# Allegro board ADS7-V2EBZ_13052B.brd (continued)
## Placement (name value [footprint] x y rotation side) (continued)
R339  0  [R0402]  172.85 12.45 180 bottom
R340  4.7K  [R0402]  21.72 124.84 90 bottom
R341  4.7K  [R0402]  151.64 15.88 180 bottom
R342  0  [R0402]  197.49 150.62 0 bottom
R343  100  [R0402]  141.48 37.34 90 bottom
R382  0  [R0402]  185.67 50.04 90 top
R486  10K  [R0402]  37.08 14.61 0 bottom
R518  10  [R0603]  178.44 155.19 180 bottom
R538  4.99K  [R0805]  186.94 150.37 270 bottom
R556  10K  [R0402]  91.44 128.52 180 bottom
R557  10K  [R0402]  87.88 132.08 90 bottom
R558  0  [R0402]  86.23 132.08 90 bottom
R559  0  [R0402]  84.07 131.44 0 bottom
R626  100  [R0201]  64.08 70.48 90 bottom
R627  100  [R0201]  65.1 69.6 90 bottom
R639  33  [R0402]  180.85 57.53 90 top
R640  33  [R0402]  179.58 57.53 90 top
R658  0  [R0402]  164.72 34.92 180 top
R660  0  [R0402]  160.78 35.56 90 top
R664  10K  [R0402]  155.57 32 0 top
R670  100  [R0201]  82.09 70.54 90 bottom
RN1  33  [RN2HV]  199.9 82.93 180 top
RN2  33  [RN2HV]  194.82 82.93 0 top
RN3  33  [RN2HV]  203.71 70.74 270 top
RN4  33  [RN2HV]  203.71 75.82 270 top
RN5  33  [RN2HV]  203.71 60.58 270 top
RN6  33  [RN2HV]  185.93 53.72 180 top
RN7  33  [RN2HV]  180.34 61.85 90 top
RN8  33  [RN2HV]  180.34 66.93 90 top
RN9  33  [RN2HV]  180.34 72.01 90 top
RN10  33  [RN2HV]  192.28 53.72 180 top
RN11  33  [RN2HV]  197.36 53.72 180 top
RN12  33  [RN2HV]  203.71 65.66 270 top
S1  1201M2S3AQE2  [SWTHRAL500W900H450]  201.8 139.06 270 top
S2  EVQ-PAC05R  [SWPANASONIC_EVQPA]  189.36 96.77 180 top
S3  EVQ-PAC05R  [SWPANASONIC_EVQPA]  99.44 24.13 0 top
S4  SDA05H1SBD  [SWSML578W295H214]  47.37 17.91 180 top
S5  EVQ-PAC05R  [SWPANASONIC_EVQPA]  86.36 14.1 0 top
S6  EVQ-PAC05R  [SWPANASONIC_EVQPA]  99.44 14.1 0 top
TP1  GRN  [CNLOOPTP]  48.9 143 0 top
TP2  GRN  [CNLOOPTP]  132.59 137.03 0 top
TP3  GRN  [CNLOOPTP]  167.77 137.03 0 top
TP4  GRN  [CNLOOPTP]  172.34 137.03 0 top
TP5  GRN  [CNLOOPTP]  184.28 118.24 0 top
TP6  GRN  [CNLOOPTP]  175.13 86.23 0 top
TP7  GRN  [CNLOOPTP]  172.09 34.42 0 top
U1  ADP5054ACPZ  [QFN48_7X7_PAD5_6X5_6]  52.58 159.77 90 top
U2  ADP5054ACPZ  [QFN48_7X7_PAD5_6X5_6]  123.7 159.77 90 top
U3  ADM1293-1AACPZ  [QFN16_4X4_PAD2_65X2_65]  16.51 146.18 0 top
U4  ADM1293-1AACPZ  [QFN16_4X4_PAD2_65X2_65]  27.81 146.18 0 top
U5  ADM1293-1AACPZ  [QFN16_4X4_PAD2_65X2_65]  65.66 146.18 0 top
U6  ADM1293-1AACPZ  [QFN16_4X4_PAD2_65X2_65]  87.5 146.18 0 top
U7  ADM1293-1AACPZ  [QFN16_4X4_PAD2_65X2_65]  96.52 146.18 0 top
U8  ADM1293-1AACPZ  [QFN16_4X4_PAD2_65X2_65]  140.97 146.18 0 top
U9  ADM1276-3ACPZ  [QFN20_5X5_PAD3_1X3_1]  192.28 151 0 top
U10  ADM1178-1ARMZ  [RM10]  19.05 124.71 0 top
U11  ADCLK944BCPZ  [QFN16_3X3_PAD1_5X1_5]  118.87 120.14 90 top
U12  AD9577ACPZ  [QFN40_6X6_PAD4_6X4_6]  132.97 118.75 0 top
U13  ADCLK944BCPZ  [QFN16_3X3_PAD1_5X1_5]  146.69 119.76 270 top
U14  ADM1293-1AACPZ  [QFN16_4X4_PAD2_65X2_65]  159.77 112.14 0 top
U15  ADM1293-1AACPZ  [QFN16_4X4_PAD2_65X2_65]  167.39 112.14 0 top
U16  ADM1293-1AACPZ  [QFN16_4X4_PAD2_65X2_65]  173.74 112.14 0 top
U17  ADM1170-2AUJZ  [TSOT-8]  20.19 101.85 180 top
U18  ADP7105ACPZ-1.8  [DFN8_3X3_PAD2_38X1_64]  179.32 104.39 270 top
U19  ADP151AUJZ-1.8-R7  [TSOT-5]  187.58 104.27 180 top
U20  ADP121-AUJZ25R7  [TSOT-5]  193.29 104.27 180 top
U21  ADP1715ARMZ-1.2-R7  [MSOP8]  205.36 104.9 270 top
U22  SN74AVC2T245RSWR  [QFN10_1_8X1_4]  142.11 99.82 0 top
U23  NC7WZ08K8X  [US8]  17.91 90.42 0 top
U24  ADM6306D131ARJZ1R7  [SOT23-5L]  175.51 93.47 0 top
U25  NC7WZ08K8X  [US8]  189.48 87.88 0 top
U26  NC7SV125P5X  [SC70-5-2]  196.09 88.14 270 top
U27  ADP5054ACPZ  [QFN48_7X7_PAD5_6X5_6]  163.19 67.56 0 top
U28  FXL4TD245BQX  [DQFN16_3_5X2_5_PAD2_15X1_15]  175.26 67.95 90 top
U29  ADSP-BF527KBCZ-6A  [CSPBGA208]  192.28 67.69 0 top
U30  NC7WZ04P6X  [SC70]  207.65 64.14 180 top
U31  XC7VX330T-3FFG1157E  [FBGA1156]  67.69 58.04 0 top
U32  ADG812YRUZ  [TSSOP16]  179.2 48.13 0 top
U33  ICS85411AMLF  [SO8]  199.26 39.75 270 top
U34  NC7SZ08M5X  [SOT23-5L]  172.72 41.91 180 top
U35  TPS51200DRCT  [SON10_3X3_PAD2_4X1_65]  159.64 31.75 0 top
U36  PCA9545APW,118  [TSSOP20]  181.48 27.05 90 top
U37  FXL4245MPX  [MLP24_4_5X3_5_PAD3_1X2_1]  154.56 18.67 270 top
U38  M24C64-WMN6TP  [SO8]  169.29 19.05 90 top
U39  TPS51200DRCT  [SON10_3X3_PAD2_4X1_65]  87.38 128.27 180 bottom
U40  SN74LVC1G17DBVR  [SOT23-5L]  175.01 120.52 90 bottom
U41  MX25U3235FM2I-10G  [SOP8_A]  185.42 39.5 0 bottom
U42  ICS85411AMLF  [SO8]  136.4 37.34 90 bottom
U43  NC7SV126P5X  [SC70-5-2]  89.92 16.51 180 bottom
U44  ADCMP671-1YUJZ  [TSOT23_6]  25.78 18.29 180 bottom
V1  27V  [R0603H35]  194.44 95.76 180 bottom
W1  WP22  [TPC45D22]  133.48 127.25 0 top
W2  WP22  [TPC45D22]  135.51 127.25 0 top
W8  WP22  [TPC45D22]  108.08 122.3 0 top
W9  WP22  [TPC45D22]  159.13 118.24 90 top
W10  WP22  [TPC45D22]  108.08 120.27 0 top
W11  WP22  [TPC45D22]  159.13 120.14 90 top
Y1  25.000MEGHZ  [YSML126W98H29]  127.89 112.01 0 top
Y2  24MEGHZ  [YSML197W126H59]  180.85 81.66 90 top

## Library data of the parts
C1 C6 C13 C19 C22 C25 C35 C44 C109 C112 C118 C119 = CAP: User Part Number: UPN; Tolerance: 10; alternate symbols: (C0402H22_ALT,C0201-2,C0402_A,C0402_ALT); part number: CAP_SM-10UF,25V,10,E011786,C1210; tolerance: 10
C2 C3 C38 C47 C49 C50 C113 C116 C117 = CAP: Tolerance: 5; User Part Number: UPN; alternate symbols: (C0402H22_ALT,C0201-2,C0402_A,C0402_ALT); part number: CAP_SM-1000PF,25V,5,E017843,C0402; tolerance: 5
C4 C5 C7-C11 C16 C17 C30-C34 C40-C43 C84 C85 C91-C94 C98 C99 = CAP: User Part Number: UPN; Tolerance: 20; alternate symbols: (C0402H22_ALT,C0201-2,C0402_A,C0402_ALT); part number: CAP_SM-100UF,6.3V,20,E006532,C1210; tolerance: 20
C12 C18 C21 C24 C56 C57 C59 C60 C63 C66 C69-C72 C75-C78 C95 C96 C101 C102 C110 C111 C125-C127 C130 C133 C135-C137 C143-C147 C165 C169 C170 C172 C177 C180-C182 C188-C192 C194 C198 C201 C202 C204 C212 C214 C216 C218 C220-C222 C224-C226 C234 C235 C244 C246 C247 C255 C257-C261 C264 C265 C267 C272 C274 C275 C278 C279 C281-C283 C286 C288 C302 C319 C326 C335 C339 C340 C342-C346 C348 = CAP: Tolerance: 10; User Part Number: UPN; alternate symbols: (C0402H22_ALT,C0201-2,C0402_A,C0402_ALT); part number: CAP_SM-0.1UF,16V,10,E007200,C0402; tolerance: 10; signal model: DEFAULT_CAPACITOR_100000pF_2_1
C14 C15 C20 C23 C26-C28 C39 C122 C123 C128 C129 = CAP: Tolerance: 20; User Part Number: UPN; alternate symbols: (C0402H22_ALT,C0201-2,C0402_A,C0402_ALT); part number: CAP_SM-47UF,16V,20,E013836,C1210-2; tolerance: 20
C29 C54 C149 = CAP: User Part Number: UPN; Tolerance: 10; alternate symbols: (C0402H22_ALT,C0201-2,C0402_A,C0402_ALT); part number: CAP_SM-0.01UF,50V,10,E000421,C0603; tolerance: 10; signal model: DEFAULT_CAPACITOR_10000pF_2_1
C36 C37 C45 C46 C79-C82 C87 C114 C115 C228 = CAP: User Part Number: UPN; Tolerance: 10; alternate symbols: (C0402H22_ALT,C0201-2,C0402_A,C0402_ALT); part number: CAP_SM-1UF,10V,10,E011783,C0603; tolerance: 10
C48 C52 C150 = CAP: User Part Number: UPN; Tolerance: 10; alternate symbols: (C0402H22_ALT,C0201-2,C0402_A,C0402_ALT); part number: CAP_SM-0.1UF,50V,10,E015248,C0603; tolerance: 10; signal model: DEFAULT_CAPACITOR_100000pF_2_1
C51 = CAP: User Part Number: UPN; Tolerance: 10; alternate symbols: (C0402H22_ALT,C0201-2,C0402_A,C0402_ALT); part number: CAP_SM-0.33UF,16V,10,E015523,C0603; tolerance: 10; signal model: DEFAULT_CAPACITOR_330000pF_2_1
C53 = CAP: User Part Number: UPN; Tolerance: 10; alternate symbols: (C0402H22_ALT,C0201-2,C0402_A,C0402_ALT); part number: CAP_SM-1UF,25V,10,E006992,C0603; tolerance: 10; signal model: DEFAULT_CAPACITOR_1e+06pF_2_1
C55 = CAP: User Part Number: UPN; Tolerance: 10; alternate symbols: (C0402H22_ALT,C0201-2,C0402_A,C0402_ALT); part number: CAP_SM-22NF,16V,10,E000327,C0603; tolerance: 10; signal model: DEFAULT_CAPACITOR_22000pF_2_1
C58 C97 C186 C291 = CAPP: User Part Number: UPN; Tolerance: 20; part number: CAPP_SM-330UF,6.3V,20,E000644,C7343H162; tolerance: 20; signal model: DEFAULT_CAPACITOR_3.3e+08pF_N_P
C61 C65 C168 C171 C173 C178 C179 C187 C195-C197 C200 C203 C213 C215 C217 C219 C232 C239 = CAP: Tolerance: 10; User Part Number: UPN; alternate symbols: (C0402H22_ALT,C0201-2,C0402_A,C0402_ALT); part number: CAP_SM-0.01UF,25V,10,E010983,C0402; tolerance: 10; signal model: DEFAULT_CAPACITOR_10000pF_2_1
C62 = CAP: Tolerance: 10; User Part Number: UPN; alternate symbols: (C0402H22_ALT,C0201-2,C0402_A,C0402_ALT); part number: CAP_SM-0.33UF,10V,10,E011273,C0402; tolerance: 10; signal model: DEFAULT_CAPACITOR_100000pF_2_1
C64 = CAP: Tolerance: 10; User Part Number: UPN; alternate symbols: (C0402H22_ALT,C0201-2,C0402_A,C0402_ALT); part number: CAP_SM-0.22UF,10V,10,E011012,C0402; tolerance: 10; signal model: DEFAULT_CAPACITOR_220000pF_2_1
C67 C68 = CAP: Tolerance: 5; User Part Number: UPN; alternate symbols: (C0402H22_ALT,C0201-2,C0402_A,C0402_ALT); part number: CAP_SM-22PF,50V,5,E000265,C0402; tolerance: 5; signal model: DEFAULT_CAPACITOR_22pF_2_1
C73 = CAP: Tolerance: 10; User Part Number: UPN; alternate symbols: (C0402H22_ALT,C0201-2,C0402_A,C0402_ALT); part number: CAP_SM-1UF,10V,10,E011429,C0402; tolerance: 10; signal model: DEFAULT_CAPACITOR_1e+06pF_1_2
C74 = CAP: Tolerance: 10; User Part Number: UPN; alternate symbols: (C0402H22_ALT,C0201-2,C0402_A,C0402_ALT); part number: CAP_SM-0.33UF,10V,10,E011273,C0402; tolerance: 10; signal model: DEFAULT_CAPACITOR_330000pF_1_2
C83 C88 = CAP: User Part Number: UPN; Tolerance: 10; alternate symbols: (C0402H22_ALT,C0201-2,C0402_A,C0402_ALT); part number: CAP_SM-2.2UF,6.3V,10,E006877,C0603; tolerance: 10
C86 = CAP: Tolerance: 10; User Part Number: UPN; alternate symbols: (C0402H22_ALT,C0201-2,C0402_A,C0402_ALT); part number: CAP_SM-0.01UF,25V,10,E019646,C0402; tolerance: 10
C89 = CAP: Tolerance: 10; User Part Number: UPN; alternate symbols: (C0402H22_ALT,C0201-2,C0402_A,C0402_ALT); part number: CAP_SM-0.01UF,25V,10,E019646,C0402; tolerance: 10; signal model: DEFAULT_CAPACITOR_10000pF_2_1
C90 = CAP: Tolerance: 10; User Part Number: UPN; alternate symbols: (C0402H22_ALT,C0201-2,C0402_A,C0402_ALT); part number: CAP_SM-4700PF,50V,10,E000289,C0402; tolerance: 10; signal model: DEFAULT_CAPACITOR_4700pF_1_2
C100 = CAP: Tolerance: 10; User Part Number: UPN; alternate symbols: (C0402H22_ALT,C0201-2,C0402_A,C0402_ALT); part number: CAP_SM-1UF,10V,10,E011429,C0402; tolerance: 10; signal model: DEFAULT_CAPACITOR_100pF_2_1
C103 C120 = CAPP: User Part Number: UPN; Tolerance: 10; part number: CAPP_SM-680UF,6.3V,10,E017133,C7343-43; tolerance: 10; signal model: DEFAULT_CAPACITOR_3.3e+08pF_N_P
C104 C106 = CAP: Tolerance: 0.5PF; User Part Number: UPN; alternate symbols: (C0402H22_ALT,C0201-2,C0402_A,C0402_ALT); part number: CAP_SM-8.2PF,50V,0.5PF,E000302,C0402; tolerance: 0.5PF; signal model: DEFAULT_CAPACITOR_8.2pF_2_1
C105 = CAP: User Part Number: UPN; Tolerance: 10; alternate symbols: (C0402H22_ALT,C0201-2,C0402_A,C0402_ALT); part number: CAP_SM-10000PF,250V,10,E011672,C0805; tolerance: 10; signal model: DEFAULT_CAPACITOR_10000pF_2_1
C107 C108 C121 C124 C132 C141 C142 C229 C230 C251-C254 C263 C273 C285 C292-C294 C303 C304 C327-C330 C336 = CAP: Tolerance: -20/+80; User Part Number: UPN; alternate symbols: (C0402H22_ALT,C0201-2,C0402_A,C0402_ALT); part number: CAP_SM-0.1UF,25V,-20/+80,E011876,C0402; tolerance: -20/+80; signal model: DEFAULT_CAPACITOR_100000pF_2_1
C131 C163 = CAP: User Part Number: UPN; Tolerance: 10; alternate symbols: (C0402H22_ALT,C0201-2,C0402_A,C0402_ALT); part number: CAP_SM-4.7UF,16V,10,E011042,C0805; tolerance: 10; signal model: DEFAULT_CAPACITOR_4.7e+06pF_2_1
C134 C164 = CAP: User Part Number: UPN; Tolerance: 5; alternate symbols: (C0402H22_ALT,C0201-2,C0402_A,C0402_ALT); part number: CAP_SM-1000PF,50V,5,E007908,C0603; tolerance: 5; signal model: DEFAULT_CAPACITOR_1000pF_2_1
C138-C140 C183-C185 = CAP: User Part Number: UPN; Tolerance: 10; alternate symbols: (C0402H22_ALT,C0201-2,C0402_A,C0402_ALT); part number: CAP_SM-10UF,25V,10,E006874,C1206; tolerance: 10; signal model: DEFAULT_CAPACITOR_1e+07pF_2_1
C148 = CAP: User Part Number: UPN; Tolerance: 10; alternate symbols: (C0402H22_ALT,C0201-2,C0402_A,C0402_ALT); part number: CAP_SM-0.033UF,16V,10,E011751,C0603; tolerance: 10; signal model: DEFAULT_CAPACITOR_33000pF_2_1
C151-C162 C206-C211 = CAP: Tolerance: 20; User Part Number: UPN; alternate symbols: (C0402H22_ALT,C0201-2,C0402_A,C0402_ALT); part number: CAP_SM-4.7UF,10V,20,E015601,C0402; tolerance: 20
C166 C167 C289 C307 = CAP: User Part Number: UPN; Tolerance: 20; alternate symbols: (C0402H22_ALT,C0201-2,C0402_A,C0402_ALT); part number: CAP_SM-100UF,6.3V,20,E006532,C1210; tolerance: 20; signal model: DEFAULT_CAPACITOR_1e+08pF_2_1
C174-C176 C193 C199 = CAP: User Part Number: UPN; Tolerance: 10; alternate symbols: (C0402H22_ALT,C0201-2,C0402_A,C0402_ALT); part number: CAP_SM-0.1UF,6.3V,10,E011567,C0201; tolerance: 10; signal model: DEFAULT_CAPACITOR_100000pF_2_1
C205 C223 C231 C318 C331 C347 = CAP: User Part Number: UPN; Tolerance: 20; alternate symbols: (C0402H22_ALT,C0201-2,C0402_A,C0402_ALT); part number: CAP_SM-10UF,6.3V,20,E011043,C0805; tolerance: 20; signal model: DEFAULT_CAPACITOR_1e+07pF_2_1
C227 C287 C295-C300 C305 C306 = CAP: Tolerance: 20; User Part Number: UPN; alternate symbols: (C0402H22_ALT,C0201-2,C0402_A,C0402_ALT); part number: CAP_SM-4.7UF,10V,20,E015601,C0402; tolerance: 20; signal model: DEFAULT_CAPACITOR_4.7e+06pF_2_1
C233 = CAP: User Part Number: UPN; Tolerance: 10; alternate symbols: (C0402H22_ALT,C0201-2,C0402_A,C0402_ALT); part number: CAP_SM-0.033UF,16V,10,E011751,C0603; tolerance: 10
C236 C238 = CAP: Tolerance: 10; User Part Number: UPN; alternate symbols: (C0402H22_ALT,C0201-2,C0402_A,C0402_ALT); part number: CAP_SM-1UF,16V,10,E019219,C0402; tolerance: 10
C237 = CAP: User Part Number: UPN; Tolerance: 10; alternate symbols: (C0402H22_ALT,C0201-2,C0402_A,C0402_ALT); part number: CAP_SM-0.33UF,16V,10,E015523,C0603; tolerance: 10
C240 = CAP: User Part Number: UPN; Tolerance: 60; alternate symbols: (C0402H22_ALT,C0201-2,C0402_A,C0402_ALT); part number: CAP_SM-47UF,6.3V,60,E000249,C1210; tolerance: 60; signal model: DEFAULT_CAPACITOR_4.7e+07pF_2_1
C241-C243 C249 C250 C262 C270 C284 C290 C301 C309 C317 = CAP: User Part Number: UPN; Tolerance: 20; alternate symbols: (C0402H22_ALT,C0201-2,C0402_A,C0402_ALT); part number: CAP_SM-100UF,6.3V,20,E016591,C1206H71; tolerance: 20; signal model: DEFAULT_CAPACITOR_1e+08pF_2_1
C245 C248 C256 C266 C268 C269 C276 C277 C280 = CAP: User Part Number: UPN; Tolerance: 10; alternate symbols: (C0402H22_ALT,C0201-2,C0402_A,C0402_ALT); part number: CAP_SM-1UF,10V,10,E011783,C0603; tolerance: 10; signal model: DEFAULT_CAPACITOR_1e+06pF_2_1
C271 = CAP: User Part Number: UPN; Tolerance: 20; alternate symbols: (C0402H22_ALT,C0201-2,C0402_A,C0402_ALT); part number: CAP_SM-47UF,6.3V,20,E006154,C1206; tolerance: 20; signal model: DEFAULT_CAPACITOR_4.7e+07pF_2_1
C308 = CAP: Tolerance: 10; User Part Number: UPN; alternate symbols: (C0402H22_ALT,C0201-2,C0402_A,C0402_ALT); part number: CAP_SM-0.1UF,16V,10,E007200,C0402; tolerance: 10
C310-C312 C314 C315 C320-C322 C324 C325 = CAP: Tolerance: 10; User Part Number: UPN; alternate symbols: (C0402H22_ALT,C0201-2,C0402_A,C0402_ALT); part number: CAP_SM-4.7UF,6.3V,10,E020089,C0402; tolerance: 10; signal model: DEFAULT_CAPACITOR_1e+06pF_2_1
C313 = CAPP: Tolerance: 20; User Part Number: UPN; part number: CAPP_SM-220UF,25V,20,E007635,CPLSML327W327H413; tolerance: 20; signal model: DEFAULT_CAPACITOR_2.2e+08pF_N_P
C316 C323 C332-C334 = CAP: Tolerance: 10; User Part Number: UPN; alternate symbols: (C0402H22_ALT,C0201-2,C0402_A,C0402_ALT); part number: CAP_SM-4.7UF,6.3V,10,E020089,C0402; tolerance: 10; signal model: DEFAULT_CAPACITOR_470000pF_2_1
C337 C338 C341 = CAP: User Part Number: UPN; Tolerance: 10; alternate symbols: (C0402H22_ALT,C0201-2,C0402_A,C0402_ALT); part number: CAP_SM-1UF,16V,10,E006882,C0603; tolerance: 10; signal model: DEFAULT_CAPACITOR_1e+06pF_2_1
CN1-CN18 = CAPARRAY8P: Tolerance: 20; User Part Number: UPN; part number: CAPARRAY8P_SM-1000PF,50V,20,E005848,C-NET8P-0805; tolerance: 20
CR1 = DIOMMSZ2V4T1: User Part Number: UPN; Tolerance: N/A; part number: DIOMMSZ2V4T1_SM-MMSZ4678T1G,1.8V,N/A,E005557,SOD123; tolerance: N/A
CR2 CR4 CR5 = DIOZNR_V2: User Part Number: UPN; Tolerance: N/A; part number: DIOZNR_V2_SM-PGB1010603,24V,N/A,E011584,D0603; tolerance: N/A
D1 = DIO: User Part Number: UPN; Tolerance: N/A; alternate symbols: (DO15_ALT); part number: DIO_SM-SMBJ13A-TR,13V,N/A,E016695,DO214AA1; tolerance: N/A
D2 = DIOSCHOTTKY: User Part Number: UPN; Tolerance: N/A; part number: DIOSCHOTTKY_SM-MBRS540T3G,40V,N/A,E010076,SMC; tolerance: N/A
D3 = DIO: User Part Number: UPN; Tolerance: N/A; alternate symbols: (DO15_ALT); part number: DIO_SM-DL4148,100V,N/A,E001135,DL35; tolerance: N/A
DS1-DS8 DS13 DS15 DS16 DS32 DS39 DS40 = DIOLED: User Part Number: UPN; Tolerance: N/A; part number: DIOLED_SM-AA2214CGSK (GREEN),2.1V,N/A,E015747,LEDSML90W55H55; tolerance: N/A
DS14 DS17 DS18 = DIOLED: User Part Number: UPN; Tolerance: N/A; part number: DIOLED_SM-AA2214SURSK (RED),1.95V,N/A,E015746,LEDSML90W55H55; tolerance: N/A
E1 E2 = FERRITE: User Part Number: UPN; Tolerance: 25; part number: FERRITE_SM-600OHM,25,E014192,L1206-3; tolerance: 25; signal model: DEFAULT_RESISTOR_600OHM_2_1
E3 = FERRITE: User Part Number: UPN; Tolerance: N/A; part number: FERRITE_SM-600OHM,N/A,E002360,L0805; tolerance: N/A; signal model: DEFAULT_RESISTOR_600OHM_2_1
F1 = FSFUSE: User Part Number: UPN; part number: FSFUSE_SM-8A,24V,E017065,TE CONNECTIVITY,1206SFF800F/24-2,SCD-015423,F1206H46,N/A
F2 = FSFUSE: User Part Number: UPN; part number: FSFUSE_SM-0.05A,60V,E017159,BEL FUSE INC,0ZCB0005FF2E,SCD-016141,F1210_A,N/A
F3 = FSFUSE: User Part Number: UPN; part number: FSFUSE_SM-0.50A,6V,E016241,LITTELFUSE,1206L050,SCD-014224,F1206H30,N/A
GP1 = NC2P: User Part Number: UPN; part number: NC2P_SM-JPSLD02,E006230,JPSLD02
J3-J6 = CNBNC5P: User Part Number: UPN; alternate symbols: (CNAMPHENOL132255-11_ALT); part number: CNBNC5P_SM-132255-11,E017863,AMPHENOL CONNEX,132255-11,SCD-016572,CNAMPHENOL132255-11
L1 = IND: Tolerance: 20; User Part Number: UPN; alternate symbols: (L0402-2,L0603_ALT); part number: IND_SM-1.8UH,20,E019861,LSML250W258H122; tolerance: 20
L2 = IND: Tolerance: 20; User Part Number: UPN; alternate symbols: (L0402-2,L0603_ALT); part number: IND_SM-3.3UH,20,E017135,LSML250W258H122; tolerance: 20
L3 L4 L7 L8 L11 L12 = IND: User Part Number: UPN; Tolerance: 20; alternate symbols: (L0402-2,L0603_ALT); part number: IND_SM-4.7UH,20,E013623,LSMSQ157H122; tolerance: 20
L5 L6 L9 L10 = IND: Tolerance: 20; User Part Number: UPN; alternate symbols: (L0402-2,L0603_ALT); part number: IND_SM-1.2UH,20,E018077,LSML208W216H122; tolerance: 20
P1 = CN400P_A_K: User Part Number: UPN; part number: CN400P_A_K_SM-ASP-134486-01,E011412,CNSAMTECASP-134486-01
P2 P11 = CN3P: User Part Number: UPN; part number: CN3P_TH-MOLEX22-23-2031,E000815,CNMOLEX22-23-2031
P3 = CN14P: User Part Number: UPN; part number: CN14P_SM-87832-1420-TB32,E005962,CNMOLEX87832-1420
P4 = CN3P: User Part Number: UPN; part number: CN3P_TH-22-11-2032,E016081,CNMOLEX22-23-2031
P5 P6 = CN204P_2GND: User Part Number: UPN; part number: CN204P_2GND_SM-AS0A626-U2SN-7F,E016579,CNFOXAS0A626-U2SN-7F
P7 = CN6P: User Part Number: UPN; part number: CN6P_TH-39-30-1060,E016920,CNHDRRA2X3H451
P8 = CN4P_2PGND: User Part Number: UPN; part number: CN4P_2PGND_TH-292304-1,E019795,CNTYCO292304
P9 = CN20P: User Part Number: UPN; part number: CN20P_TH-CA-D20-24C-44,E000760,CNBERG2X10H346LD36
P10 = CN14P_ODD_EVEN: User Part Number: UPN; part number: CN14P_ODD_EVEN_SM-TSM-107-01-T-DV,E019809,CNHDR2X7H380
Q1 Q2 Q7 = TRANNMOSFET_DUAL: User Part Number: UPN; part number: TRANNMOSFET_DUAL_SM-BSC072N03LD G,E019375,PG-TDSON-8_A
Q3 = TRANBSC079: User Part Number: UPN; part number: TRANBSC079_SM-PSMN0R9-25YLC,115,E016708,SOT669
Q4 Q5 = TRANSI4864: User Part Number: UPN; part number: TRANSI4864_SM-PSMN013-30LL,E016707,SOT873-1
Q6 = TRANSI2301DS: User Part Number: UPN; part number: TRANSI2301DS_SM-SI2333DS-T1-E3,E013954,SOT23
Q8-Q10 Q14-Q16 = TRANBSS138: User Part Number: UPN; part number: TRANBSS138_SM-NDS331N,E012840,SOT23
Q11 Q12 = TRANNDS332P: User Part Number: UPN; part number: TRANNDS332P_SM-NDS332P,E004675,SOT23
Q13 = TRANNMOSFET_V8: User Part Number: UPN; part number: TRANNMOSFET_V8_SM-SI2336DS-T1-GE3,E017134,SOT23
R1 R13 R19 R127 = RES: Tolerance: 1; User Part Number: UPN; alternate symbols: (RRAD984L1500W75H520LD32;TO220H590_ALT;R0402_A;R0603_A); part number: RES_SM-0.001,E019910,1W,1,STACKPOLE ELECTRONICS,CSNL1206FT1L00,SCD-017771,R1206,N/A; tolerance: 1
R2-R4 R6 R20 R21 R25 R26 R34 R37 R45 R129 R146 R148-R150 R267 = RES: Tolerance: 1; User Part Number: UPN; alternate symbols: (RRAD984L1500W75H520LD32;TO220H590_ALT;R0402_A;R0603_A); part number: RES_SM-10K,E003751,1/16W,1,PANASONIC,ERJ-2RKF1002X,SCD-001006,R0402,N/A; tolerance: 1
R5 R8 R147 = RES: Tolerance: 1; User Part Number: UPN; alternate symbols: (RRAD984L1500W75H520LD32;TO220H590_ALT;R0402_A;R0603_A); part number: RES_SM-499K,E019889,1/10W,1,PANASONIC,ERJ-2RKF4993X,SCD-001006,R0402,N/A; tolerance: 1
R7 R43 R213 = RES: Tolerance: 1; User Part Number: UPN; alternate symbols: (RRAD984L1500W75H520LD32;TO220H590_ALT;R0402_A;R0603_A); part number: RES_SM-200K,E004033,1/16W,1,PANASONIC,ERJ-2RKF2003X,SCD-001006,R0402,N/A; tolerance: 1
R9 R10 R14 R15 R44 R111 R143 = RES: Tolerance: 1; User Part Number: UPN; alternate symbols: (RRAD984L1500W75H520LD32;TO220H590_ALT;R0402_A;R0603_A); part number: RES_SM-22.1K,E007152,1/16W,1,VISHAY,CRCW040222K1FKED,SCD-001663,R0402,N/A; tolerance: 1
R11 R12 R16 R157 R158 = RES: Tolerance: 1; User Part Number: UPN; alternate symbols: (RRAD984L1500W75H520LD32;TO220H590_ALT;R0402_A;R0603_A); part number: RES_SM-0.015,E019913,1/4W,1,SUSUMU,RL0816T-R015-F,SCD-017773,R0603,N/A; tolerance: 1
R17 R29 R51 R58 = RES: User Part Number: UPN; Tolerance: 1; alternate symbols: (RRAD984L1500W75H520LD32;TO220H590_ALT;R0402_A;R0603_A); part number: RES_SM-51.1K,E003601,1/8W,1,PANASONIC,ERJ-6ENF5112V,SCD-001006,R0805,N/A; tolerance: 1; signal model: DEFAULT_RESISTOR_51100OHM_2_1
R18 = RES: User Part Number: UPN; Tolerance: 1; alternate symbols: (RRAD984L1500W75H520LD32;TO220H590_ALT;R0402_A;R0603_A); part number: RES_SM-6.65K,E003537,1/8W,1,PANASONIC,ERJ-6ENF6651V,SCD-001006,R0805,N/A; tolerance: 1; signal model: DEFAULT_RESISTOR_6650OHM_2_1
R22 R30 R31 R36 R39-R41 R48 R49 R54 R120 R209 R210 R264 R266 R286 R288 R289 R291 = RES: Tolerance: 5; User Part Number: UPN; alternate symbols: (RRAD984L1500W75H520LD32;TO220H590_ALT;R0402_A;R0603_A); part number: RES_SM-0,E003438,1/16W,5,PANASONIC,ERJ-2GE0R00X,SCD-002744,R0402,N/A; tolerance: 5
R23 = RES: Tolerance: 1; User Part Number: UPN; alternate symbols: (RRAD984L1500W75H520LD32;TO220H590_ALT;R0402_A;R0603_A); part number: RES_SM-8.87K,E019975,1/10W,1,PANASONIC,ERJ-2RKF8871X,SCD-001006,R0402,N/A; tolerance: 1
R24 R33 R207 R279 R280 = RES: Tolerance: 1; User Part Number: UPN; alternate symbols: (RRAD984L1500W75H520LD32;TO220H590_ALT;R0402_A;R0603_A); part number: RES_SM-10.2K,E019451,1/16W,1,VISHAY,CRCW040210K2FKED,SCD-001663,R0402,N/A; tolerance: 1
R27 R211 R245 R518 = RES: Tolerance: 1; User Part Number: UPN; alternate symbols: (RRAD984L1500W75H520LD32;TO220H590_ALT;R0402_A;R0603_A); part number: RES_SM-10,E003666,1/10W,1,PANASONIC,ERJ-3EKF10R0V,SCD-001006,R0603,N/A; tolerance: 1; signal model: DEFAULT_RESISTOR_10OHM_2_1
R28 R133 R144 R145 R159 R160 R163 R164 R171-R173 R178-R189 R191 R193 R197 R198 R200 R204 R205 R218 R219 R223 R240-R243 R246 R256 R268 R281 R282 R296 R305 R310 R311 R316-R320 R323 R335 R340 R341 = RES: Tolerance: 1; User Part Number: UPN; alternate symbols: (RRAD984L1500W75H520LD32;TO220H590_ALT;R0402_A;R0603_A); part number: RES_SM-4.7K,E008190,1/16W,1,PANASONIC,ERJ-2RKF4701X,SCD-001006,R0402,N/A; tolerance: 1; signal model: DEFAULT_RESISTOR_4700OHM_2_1
R32 = RES: Tolerance: 1; User Part Number: UPN; alternate symbols: (RRAD984L1500W75H520LD32;TO220H590_ALT;R0402_A;R0603_A); part number: RES_SM-31.6K,E013702,1/10W,1,PANASONIC,ERJ-3EKF3162V,SCD-001006,R0603,N/A; tolerance: 1
R35 = RES: Tolerance: 1; User Part Number: UPN; alternate symbols: (RRAD984L1500W75H520LD32;TO220H590_ALT;R0402_A;R0603_A); part number: RES_SM-15K,E007441,1/16W,1,PANASONIC,ERJ-2RKF1502X,SCD-001006,R0402,N/A; tolerance: 1
R38 = RES: Tolerance: 1; User Part Number: UPN; alternate symbols: (RRAD984L1500W75H520LD32;TO220H590_ALT;R0402_A;R0603_A); part number: RES_SM-4.99K,E006643,1/16W,1,PANASONIC,ERJ-2RKF4991X,SCD-001006,R0402,N/A; tolerance: 1
R42 R121 R122 = RES: Tolerance: 1; User Part Number: UPN; alternate symbols: (RRAD984L1500W75H520LD32;TO220H590_ALT;R0402_A;R0603_A); part number: RES_SM-100K,E003796,1/16W,1,PANASONIC,ERJ-2RKF1003X,SCD-001006,R0402,N/A; tolerance: 1
R46 R216 R217 = RES: Tolerance: 1; User Part Number: UPN; alternate symbols: (RRAD984L1500W75H520LD32;TO220H590_ALT;R0402_A;R0603_A); part number: RES_SM-38.3K,E016739,1/10W,1,PANASONIC,ERJ-2RKF3832X,SCD-001006,R0402,N/A; tolerance: 1
R47 = RES: Tolerance: 1; User Part Number: UPN; alternate symbols: (RRAD984L1500W75H520LD32;TO220H590_ALT;R0402_A;R0603_A); part number: RES_SM-3.3K,E010034,1/10W,1,PANASONIC,ERJ-2RKF3301X,SCD-001006,R0402,N/A; tolerance: 1
R50 = RES: Tolerance: 1; User Part Number: UPN; alternate symbols: (RRAD984L1500W75H520LD32;TO220H590_ALT;R0402_A;R0603_A); part number: RES_SM-0.001,E016694,3W,1,WELWYN,ULR3-R001FT2,SCD-015836,R2512H31,N/A; tolerance: 1; signal model: DEFAULT_RESISTOR_0.001OHM_2_1
R52 R199 = RES: Tolerance: 0.1; User Part Number: UPN; alternate symbols: (RRAD984L1500W75H520LD32;TO220H590_ALT;R0402_A;R0603_A); part number: RES_SM-1K,E005978,1/16W,0.1,SUSUMU,RG1005P-102-B-T5,SCD-002134,R0402,N/A; tolerance: 0.1; signal model: DEFAULT_RESISTOR_300OHM_2_1
R53 R55-R57 R110 R221 = RES: Tolerance: 1; User Part Number: UPN; alternate symbols: (RRAD984L1500W75H520LD32;TO220H590_ALT;R0402_A;R0603_A); part number: RES_SM-147K,E006339,1/16W,1,PANASONIC,ERJ-2RKF1473X,SCD-001006,R0402,N/A; tolerance: 1
R59 = RES: User Part Number: UPN; Tolerance: 1; alternate symbols: (RRAD984L1500W75H520LD32;TO220H590_ALT;R0402_A;R0603_A); part number: RES_SM-47K,E003636,1/8W,1,YAGEO-PHYCOMP,9C08052A4702FKHFT,NONE,R0805,N/A; tolerance: 1; signal model: DEFAULT_RESISTOR_51100OHM_2_1
R60 = RES: Tolerance: 1; User Part Number: UPN; alternate symbols: (RRAD984L1500W75H520LD32;TO220H590_ALT;R0402_A;R0603_A); part number: RES_SM-4.02K,E003122,1/4W,1,PANASONIC,ERJ-8ENF4021V,SCD-001006,R1206,N/A; tolerance: 1; signal model: DEFAULT_RESISTOR_3830OHM_2_1
R61 R118 R119 R126 R132 R165 R176 R194-R196 R201-R203 R321 R334 = RES: Tolerance: 5; User Part Number: UPN; alternate symbols: (RRAD984L1500W75H520LD32;TO220H590_ALT;R0402_A;R0603_A); part number: RES_SM-300,E003444,1/16W,5,PANASONIC,ERJ-2GEJ301X,SCD-002744,R0402,N/A; tolerance: 5; signal model: DEFAULT_RESISTOR_300OHM_2_1
R62 R65 = RES: Tolerance: 1; User Part Number: UPN; alternate symbols: (RRAD984L1500W75H520LD32;TO220H590_ALT;R0402_A;R0603_A); part number: RES_SM-4.64K,E006226,1/16W,1,PANASONIC,ERJ-2RKF4641X,SCD-001006,R0402,N/A; tolerance: 1; signal model: DEFAULT_RESISTOR_4640OHM_2_1
R63 R66 R98-R103 R105 R107 = RES: Tolerance: 0.1; User Part Number: UPN; alternate symbols: (RRAD984L1500W75H520LD32;TO220H590_ALT;R0402_A;R0603_A); part number: RES_SM-10K,E012474,1/16W,0.1,VISHAY,TNPW040210K0BEED,SCD-003272,R0402,N/A; tolerance: 0.1; signal model: DEFAULT_RESISTOR_10000OHM_2_1
R64 R69 R71 R72 R74 R75 R77-R79 R82 R83 R86 R87 R90 R94 R97 R225 R226 R237 R238 = RES: Tolerance: 1; User Part Number: UPN; alternate symbols: (RRAD984L1500W75H520LD32;TO220H590_ALT;R0402_A;R0603_A); part number: RES_SM-200,E003753,1/16W,1,PANASONIC,ERJ-2RKF2000X,SCD-001006,R0402,N/A; tolerance: 1; signal model: DEFAULT_RESISTOR_200OHM_2_1
R67 R68 R80 R81 R84 R85 R88 R89 R95 R96 R136 R260-R263 R284 R285 R639 R640 = RES: Tolerance: 0.5; User Part Number: UPN; alternate symbols: (RRAD984L1500W75H520LD32;TO220H590_ALT;R0402_A;R0603_A); part number: RES_SM-33,E012477,1/16W,0.5,YAGEO,RT0402DRE0733RL,SCD-002985,R0402,N/A; tolerance: 0.5; signal model: DEFAULT_RESISTOR_33OHM_2_1
R70 R236 = RES: Tolerance: 1; User Part Number: UPN; alternate symbols: (RRAD984L1500W75H520LD32;TO220H590_ALT;R0402_A;R0603_A); part number: RES_SM-100,E003760,1/16W,1,VENKEL,CR0402-16W-1000FPT,NONE,R0402,N/A; tolerance: 1; signal model: DEFAULT_RESISTOR_100OHM_2_1
R73 R76 R91 R134 R135 R142 R152-R156 R161 R162 R166 R167 R175 R214 R227-R230 R239 R326 R327 R338 R339 R342 R382 R558 R559 R658 R660 = RES: Tolerance: 5; User Part Number: UPN; alternate symbols: (RRAD984L1500W75H520LD32;TO220H590_ALT;R0402_A;R0603_A); part number: RES_SM-0,E003438,1/16W,5,PANASONIC,ERJ-2GE0R00X,SCD-002744,R0402,N/A; tolerance: 5; signal model: DEFAULT_RESISTOR_0.001OHM_2_1
R92 = RES: Tolerance: 1; User Part Number: UPN; alternate symbols: (RRAD984L1500W75H520LD32;TO220H590_ALT;R0402_A;R0603_A); part number: RES_SM-1MEG,E003749,1/16W,1,PANASONIC,ERJ-2RKF1004X,SCD-001006,R0402,N/A; tolerance: 1; signal model: DEFAULT_RESISTOR_1e+06OHM_2_1
R93 R235 = RES: Tolerance: 1; User Part Number: UPN; alternate symbols: (RRAD984L1500W75H520LD32;TO220H590_ALT;R0402_A;R0603_A); part number: RES_SM-1K,E003763,1/10W,1,PANASONIC,ERJ-2RKF1001X,SCD-001006,R0402,N/A; tolerance: 1; signal model: DEFAULT_RESISTOR_1000OHM_2_1
R104 R106 R108 R109 R114-R117 = RES: Tolerance: 1; User Part Number: UPN; alternate symbols: (RRAD984L1500W75H520LD32;TO220H590_ALT;R0402_A;R0603_A); part number: RES_SM-2.40K,E003787,1/16W,1,YAGEO,9C04021A2401FLHF3,NONE,R0402,N/A; tolerance: 1; signal model: DEFAULT_RESISTOR_2400OHM_2_1
R112 R290 = RES: Tolerance: 1; User Part Number: UPN; alternate symbols: (RRAD984L1500W75H520LD32;TO220H590_ALT;R0402_A;R0603_A); part number: RES_SM-31.6K,E019881,1/10W,1,PANASONIC,ERJ-2RKF3162X,SCD-001006,R0402,N/A; tolerance: 1
R113 = RES: Tolerance: 5; User Part Number: UPN; alternate symbols: (RRAD984L1500W75H520LD32;TO220H590_ALT;R0402_A;R0603_A); part number: RES_SM-0,E010093,1/4W,5,VISHAY,CRCW12060000Z0EA,SCD-001663,R1206,N/A; tolerance: 5; signal model: DEFAULT_RESISTOR_0.001OHM_2_1
R123 R170 R177 R212 R222 R224 R232 R234 R259 R322 R486 R556 R557 R664 = RES: Tolerance: 1; User Part Number: UPN; alternate symbols: (RRAD984L1500W75H520LD32;TO220H590_ALT;R0402_A;R0603_A); part number: RES_SM-10K,E003751,1/16W,1,PANASONIC,ERJ-2RKF1002X,SCD-001006,R0402,N/A; tolerance: 1; signal model: DEFAULT_RESISTOR_10000OHM_2_1
R124 = RES: Tolerance: 5; User Part Number: UPN; alternate symbols: (RRAD984L1500W75H520LD32;TO220H590_ALT;R0402_A;R0603_A); part number: RES_SM-10K,E017176,1/10W,5,PANASONIC,ERJ-2GEJ103X,SCD-001006,R0402,N/A; tolerance: 5; signal model: DEFAULT_RESISTOR_10000OHM_1_2
R125 = RES: Tolerance: 1; User Part Number: UPN; alternate symbols: (RRAD984L1500W75H520LD32;TO220H590_ALT;R0402_A;R0603_A); part number: RES_SM-10,E003768,1/16W,1,PANASONIC,ERJ-2RKF10R0X,SCD-001006,R0402,N/A; tolerance: 1; signal model: DEFAULT_RESISTOR_10OHM_1_2
R128 R272 R274 = RES: Tolerance: 1; User Part Number: UPN; alternate symbols: (RRAD984L1500W75H520LD32;TO220H590_ALT;R0402_A;R0603_A); part number: RES_SM-1K,E003763,1/10W,1,PANASONIC,ERJ-2RKF1001X,SCD-001006,R0402,N/A; tolerance: 1
R130 = RES: Tolerance: 1; User Part Number: UPN; alternate symbols: (RRAD984L1500W75H520LD32;TO220H590_ALT;R0402_A;R0603_A); part number: RES_SM-18K,E003784,1/16W,1,YAGEO,9C04021A1802FLHF3,NONE,R0402,N/A; tolerance: 1
R131 = RES: Tolerance: 2; User Part Number: UPN; alternate symbols: (RRAD984L1500W75H520LD32;TO220H590_ALT;R0402_A;R0603_A); part number: RES_SM-0,E004056,1/4W,2,WELWYN,0R0 WCR 1206,NONE,R1206,N/A; tolerance: 2
R137 R138 = RES: Tolerance: 0.1; User Part Number: UPN; alternate symbols: (RRAD984L1500W75H520LD32;TO220H590_ALT;R0402_A;R0603_A); part number: RES_SM-330,E003960,1/10W,0.1,PANASONIC,ERA-3YEB331V,SCD-001690,R0603,N/A; tolerance: 0.1; signal model: DEFAULT_RESISTOR_330OHM_2_1
R139 = RES: Tolerance: 1; User Part Number: UPN; alternate symbols: (RRAD984L1500W75H520LD32;TO220H590_ALT;R0402_A;R0603_A); part number: RES_SM-1MEG,E003682,1/10W,1,PANASONIC,ERJ-3EKF1004V,SCD-001006,R0603,N/A; tolerance: 1; signal model: DEFAULT_RESISTOR_1e+06OHM_2_1
R140 R141 R174 R275-R278 R299 R300 R302 R314 = RES: Tolerance: 1; User Part Number: UPN; alternate symbols: (RRAD984L1500W75H520LD32;TO220H590_ALT;R0402_A;R0603_A); part number: RES_SM-100K,E003796,1/16W,1,PANASONIC,ERJ-2RKF1003X,SCD-001006,R0402,N/A; tolerance: 1; signal model: DEFAULT_RESISTOR_100000OHM_2_1
R151 R190 R192 R315 = RES: Tolerance: 1; User Part Number: UPN; alternate symbols: (RRAD984L1500W75H520LD32;TO220H590_ALT;R0402_A;R0603_A); part number: RES_SM-100,E016329,1/10W,1,PANASONIC,ERJ-2RKF1000X,SCD-001006,R0402,N/A; tolerance: 1; signal model: DEFAULT_RESISTOR_100OHM_2_1
R168 R169 R306 R307 = RES: Tolerance: 1; User Part Number: UPN; alternate symbols: (RRAD984L1500W75H520LD32;TO220H590_ALT;R0402_A;R0603_A); part number: RES_SM-1K,E003763,1/10W,1,PANASONIC,ERJ-2RKF1001X,SCD-001006,R0402,N/A; tolerance: 1; signal model: DEFAULT_RESISTOR_1210OHM_2_1
R206 = RES: Tolerance: 1; User Part Number: UPN; alternate symbols: (RRAD984L1500W75H520LD32;TO220H590_ALT;R0402_A;R0603_A); part number: RES_SM-1K,E015180,1/4W,1,VISHAY,CRCW06031K00FKEAHP,SCD-014355,R0603,N/A; tolerance: 1; signal model: DEFAULT_RESISTOR_1000OHM_2_1
R208 = RES: Tolerance: 1; User Part Number: UPN; alternate symbols: (RRAD984L1500W75H520LD32;TO220H590_ALT;R0402_A;R0603_A); part number: RES_SM-12.7K,E019976,1/10W,1,PANASONIC,ERJ-2RKF1272X,SCD-001006,R0402,N/A; tolerance: 1
R215 R220 = RES: Tolerance: 1; User Part Number: UPN; alternate symbols: (RRAD984L1500W75H520LD32;TO220H590_ALT;R0402_A;R0603_A); part number: RES_SM-2K,E003752,1/16W,1,PANASONIC,ERJ-2RKF2001X,SCD-001006,R0402,N/A; tolerance: 1; signal model: DEFAULT_RESISTOR_0.001OHM_2_1
R231 = RES: Tolerance: 1; User Part Number: UPN; alternate symbols: (RRAD984L1500W75H520LD32;TO220H590_ALT;R0402_A;R0603_A); part number: RES_SM-2,E014142,1/4W,1,PANASONIC,ERJ-8RQF2R0V,SCD-001006,R1206,N/A; tolerance: 1; signal model: DEFAULT_RESISTOR_2OHM_2_1
R233 = RES: Tolerance: 1; User Part Number: UPN; alternate symbols: (RRAD984L1500W75H520LD32;TO220H590_ALT;R0402_A;R0603_A); part number: RES_SM-3.48K,E003694,1/10W,1,PANASONIC,ERJ-3EKF3481V,SCD-001006,R0603,N/A; tolerance: 1; signal model: DEFAULT_RESISTOR_3480OHM_2_1
R244 = RES: Tolerance: 1; User Part Number: UPN; alternate symbols: (RRAD984L1500W75H520LD32;TO220H590_ALT;R0402_A;R0603_A); part number: RES_SM-22,E004223,1/16W,1,MULTICOMP,MC 0.063W 0603 1% 22R.,SCD-003454,R0603,N/A; tolerance: 1; signal model: DEFAULT_RESISTOR_22OHM_2_1
R247 = RES: Tolerance: 1; User Part Number: UPN; alternate symbols: (RRAD984L1500W75H520LD32;TO220H590_ALT;R0402_A;R0603_A); part number: RES_SM-76.8K,E006340,1/16W,1,PANASONIC,ERJ-2RKF7682X,SCD-001006,R0402,N/A; tolerance: 1
R248-R255 R292 R293 R297 R298 = RES: Tolerance: 1; User Part Number: UPN; alternate symbols: (RRAD984L1500W75H520LD32;TO220H590_ALT;R0402_A;R0603_A); part number: RES_SM-80.6,E003675,1/10W,1,PANASONIC,ERJ-3EKF80R6V,SCD-001006,R0603,N/A; tolerance: 1; signal model: DEFAULT_RESISTOR_80.6OHM_2_1
R257 = RES: Tolerance: 1; User Part Number: UPN; alternate symbols: (RRAD984L1500W75H520LD32;TO220H590_ALT;R0402_A;R0603_A); part number: RES_SM-100K,E010279,1/10W,1,PANASONIC,ERJ-3EKF1003V,SCD-001006,R0603,N/A; tolerance: 1; signal model: DEFAULT_RESISTOR_100000OHM_2_1
R258 = RES: Tolerance: 1; User Part Number: UPN; alternate symbols: (RRAD984L1500W75H520LD32;TO220H590_ALT;R0402_A;R0603_A); part number: RES_SM-23.2K,E013527,1/10W,1,PANASONIC,ERJ-3EKF2322V,SCD-001006,R0603,N/A; tolerance: 1; signal model: DEFAULT_RESISTOR_63400OHM_2_1
R265 = RES: Tolerance: 0.1; User Part Number: UPN; alternate symbols: (RRAD984L1500W75H520LD32;TO220H590_ALT;R0402_A;R0603_A); part number: RES_SM-2.49K,E020333,1/16W,0.1,VISHAY,TNPW04022K49BEED,HTTP://WWMFG.ANALOG.COM/WWMFG/APPS/HLM/ATTACHMENT/VIEW/215042,R0402,N/A; tolerance: 0.1
R269-R271 R283 R294 R295 R303 R312 R313 R343 = RES: Tolerance: 1; User Part Number: UPN; alternate symbols: (RRAD984L1500W75H520LD32;TO220H590_ALT;R0402_A;R0603_A); part number: RES_SM-100,E016329,1/10W,1,PANASONIC,ERJ-2RKF1000X,SCD-001006,R0402,N/A; tolerance: 1
R273 = RES: Tolerance: 1; User Part Number: UPN; alternate symbols: (RRAD984L1500W75H520LD32;TO220H590_ALT;R0402_A;R0603_A); part number: RES_SM-0.08,E020030,1/4W,1,VISHAY,WSL1206R0800FEA,SCD-001473,R1206,N/A; tolerance: 1; signal model: DEFAULT_RESISTOR_0.04OHM_1_2
R287 = RES: Tolerance: 1; User Part Number: UPN; alternate symbols: (RRAD984L1500W75H520LD32;TO220H590_ALT;R0402_A;R0603_A); part number: RES_SM-13K,E018003,1/10W,1,PANASONIC,ERJ-2RKF1302X,SCD-001006,R0402,N/A; tolerance: 1
R301 R331 R626 R627 R670 = RES: Tolerance: 1; User Part Number: UPN; alternate symbols: (RRAD984L1500W75H520LD32;TO220H590_ALT;R0402_A;R0603_A); part number: RES_SM-100,E007239,1/20W,1,PANASONIC,ERJ-1GEF1000C,SCD-001006,R0201,N/A; tolerance: 1
R304 = RES: Tolerance: 5; User Part Number: UPN; alternate symbols: (RRAD984L1500W75H520LD32;TO220H590_ALT;R0402_A;R0603_A); part number: RES_SM-330,E003462,1/16W,5,PANASONIC,ERJ-2GEJ331X,SCD-002744,R0402,N/A; tolerance: 5; signal model: DEFAULT_RESISTOR_330OHM_2_1
R308 R309 = RES: Tolerance: 1; User Part Number: UPN; alternate symbols: (RRAD984L1500W75H520LD32;TO220H590_ALT;R0402_A;R0603_A); part number: RES_SM-1.21K,E006550,1/16W,1,PANASONIC,ERJ-2RKF1211X,SCD-001006,R0402,N/A; tolerance: 1; signal model: DEFAULT_RESISTOR_4700OHM_2_1
R324 R336 = RES: Tolerance: 1; User Part Number: UPN; alternate symbols: (RRAD984L1500W75H520LD32;TO220H590_ALT;R0402_A;R0603_A); part number: RES_SM-40.2K,E006353,1/16W,1,PANASONIC,ERJ-2RKF4022X,SCD-001006,R0402,N/A; tolerance: 1; signal model: DEFAULT_RESISTOR_40200OHM_2_1
R325 = RES: Tolerance: 1; User Part Number: UPN; alternate symbols: (RRAD984L1500W75H520LD32;TO220H590_ALT;R0402_A;R0603_A); part number: RES_SM-10.5K,E007860,1/16W,1,PANASONIC,ERJ-2RKF1052X,SCD-001006,R0402,N/A; tolerance: 1; signal model: DEFAULT_RESISTOR_10500OHM_2_1
R328 = RES: Tolerance: 1; User Part Number: UPN; alternate symbols: (RRAD984L1500W75H520LD32;TO220H590_ALT;R0402_A;R0603_A); part number: RES_SM-1.21K,E006550,1/16W,1,PANASONIC,ERJ-2RKF1211X,SCD-001006,R0402,N/A; tolerance: 1; signal model: DEFAULT_RESISTOR_100000OHM_2_1
R329 = RES: Tolerance: 1; User Part Number: UPN; alternate symbols: (RRAD984L1500W75H520LD32;TO220H590_ALT;R0402_A;R0603_A); part number: RES_SM-1.21K,E006550,1/16W,1,PANASONIC,ERJ-2RKF1211X,SCD-001006,R0402,N/A; tolerance: 1; signal model: DEFAULT_RESISTOR_76800OHM_2_1
R330 R332 R333 = RES: Tolerance: 1; User Part Number: UPN; alternate symbols: (RRAD984L1500W75H520LD32;TO220H590_ALT;R0402_A;R0603_A); part number: RES_SM-1.21K,E006550,1/16W,1,PANASONIC,ERJ-2RKF1211X,SCD-001006,R0402,N/A; tolerance: 1; signal model: DEFAULT_RESISTOR_1210OHM_2_1
R337 = RES: Tolerance: 1; User Part Number: UPN; alternate symbols: (RRAD984L1500W75H520LD32;TO220H590_ALT;R0402_A;R0603_A); part number: RES_SM-36K,E003785,1/16W,1,YAGEO,9C04021A3602FLHF3,NONE,R0402,N/A; tolerance: 1; signal model: DEFAULT_RESISTOR_36000OHM_2_1
R538 = RES: User Part Number: UPN; Tolerance: 1; alternate symbols: (RRAD984L1500W75H520LD32;TO220H590_ALT;R0402_A;R0603_A); part number: RES_SM-4.99K,E003493,1/8W,1,PANASONIC,ERJ-6ENF4991V,SCD-001006,R0805,N/A; tolerance: 1; signal model: DEFAULT_RESISTOR_5620OHM_2_1
RN1-RN12 = RESNET_16P_8R: User Part Number: UPN; Tolerance: 5; part number: RESNET_16P_8R_SM-33,E014183,1/16W,5,PANASONIC,EXB-2HV330JV,SCD-002745,RN2HV,N/A; tolerance: 5
S1 = SWDPDT_2GND: User Part Number: UPN; part number: SWDPDT_2GND_TH-1201M2S3AQE2,E018708,SWTHRAL500W900H450
S2 S3 S5 S6 = SWSPST4PIN_B: User Part Number: UPN; part number: SWSPST4PIN_B_TH-EVQ-PAC05R,E006984,SWPANASONIC_EVQPA
S4 = SWSPST10PIN: User Part Number: UPN; part number: SWSPST10PIN_SM-SDA05H1SBD,E015357,SWSML578W295H214
TP1-TP7 = CNTP1P: User Part Number: UPN; alternate symbols: (CNBANANA_ALT); part number: CNTP1P_TH-GRN,E000952,CNLOOPTP
U1 U2 U27 = ADP5054: User Part Number: UPN; part number: ADP5054_SM-ADP5054ACPZ,E019222,QFN48_7X7_PAD5_6X5_6,N/A
U3-U8 U14-U16 = ADM1293: User Part Number: UPN; part number: ADM1293_SM-ADM1293-1AACPZ,E019874,QFN16_4X4_PAD2_65X2_65,N/A
U9 = ADM1276: User Part Number: UPN; part number: ADM1276_SM-ADM1276-3ACPZ,E016716,QFN20_5X5_PAD3_1X3_1,N/A
U10 = ADM1178: User Part Number: UPN; part number: ADM1178_SM-ADM1178-1ARMZ,E016603,RM10,N/A
U11 U13 = ADCLK944: User Part Number: UPN; part number: ADCLK944_SM-ADCLK944BCPZ,E011161,QFN16_3X3_PAD1_5X1_5,N/A
U12 = AD9577: User Part Number: UPN; part number: AD9577_SM-AD9577ACPZ,E014070,QFN40_6X6_PAD4_6X4_6,N/A
U17 = ADM1170: User Part Number: UPN; part number: ADM1170_SM-ADM1170-2AUJZ,E017494,TSOT-8,N/A
U18 = ADP7105: User Part Number: UPN; part number: ADP7105_SM-ADP7105ACPZ-1.8,E019350,DFN8_3X3_PAD2_38X1_64,N/A
U19 = ADP120_V2: User Part Number: UPN; part number: ADP120_V2_SM-ADP151AUJZ-1.8-R7,E013337,TSOT-5,N/A
U20 = ADP121: User Part Number: UPN; part number: ADP121_SM-ADP121-AUJZ25R7,E013944,TSOT-5,N/A
U21 = ADP1715B: User Part Number: UPN; part number: ADP1715B_SM-ADP1715ARMZ-1.2-R7,E006104,MSOP8,N/A
U22 = SN74AVC2T245: User Part Number: UPN; part number: SN74AVC2T245_SM-SN74AVC2T245RSWR,E010916,QFN10_1_8X1_4
U23 U25 = ICNC7WZ08K: User Part Number: UPN; part number: ICNC7WZ08K_SM-NC7WZ08K8X,E013671,US8
U24 = ADM6306: User Part Number: UPN; part number: ADM6306_SM-ADM6306D131ARJZ1R7,E015500,SOT23-5L,N/A
U26 = CMOSNC7SZ125: User Part Number: UPN; part number: CMOSNC7SZ125_SM-NC7SV125P5X,E017014,SC70-5-2
U28 = ICFXL4TD245: User Part Number: UPN; part number: ICFXL4TD245_SM-FXL4TD245BQX,E014936,DQFN16_3_5X2_5_PAD2_15X1_15
U29 = ADSP_BF52X_V3: User Part Number: UPN; part number: ADSP_BF52X_V3_SM-ADSP-BF527KBCZ-6A,E010177,CSPBGA208,N/A
U30 = NC7WZ04P6X: User Part Number: UPN; part number: NC7WZ04P6X_SM-NC7WZ04P6X,E002058,SC70
U31 = ICXC7VX330T: User Part Number: UPN; part number: ICXC7VX330T_SM-XC7VX330T-3FFG1157E,E018887,FBGA1156
U32 = ADG812: User Part Number: UPN; part number: ADG812_SM-ADG812YRUZ,E019850,TSSOP16,N/A
U33 U42 = ICICS85411: User Part Number: UPN; part number: ICICS85411_SM-ICS85411AMLF,E018223,SO8
U34 = NL17SZ08_V2: User Part Number: UPN; part number: NL17SZ08_V2_SM-NC7SZ08M5X,E010807,SOT23-5L
U35 U39 = ICTPS51200: User Part Number: UPN; part number: ICTPS51200_SM-TPS51200DRCT,E016607,SON10_3X3_PAD2_4X1_65
U36 = ICPCA9545: User Part Number: UPN; part number: ICPCA9545_SM-PCA9545APW,118,E015926,TSSOP20
U37 = ICFXL4245: User Part Number: UPN; part number: ICFXL4245_SM-FXL4245MPX,E014925,MLP24_4_5X3_5_PAD3_1X2_1
U38 = ICM24CXX: User Part Number: UPN; part number: ICM24CXX_SM-M24C64-WMN6TP,E013295,SO8
U40 = 74LVC1G17: User Part Number: UPN; part number: 74LVC1G17_SM-SN74LVC1G17DBVR,E007630,SOT23-5L
U41 = ICMX25U3235F: User Part Number: UPN; part number: ICMX25U3235F_SM-MX25U3235FM2I-10G,E019875,SOP8_A
U43 = ICNC7SZ126: User Part Number: UPN; part number: ICNC7SZ126_SM-NC7SV126P5X,E015499,SC70-5-2
U44 = ADCMP671: User Part Number: UPN; part number: ADCMP671_SM-ADCMP671-1YUJZ,E016765,TSOT23_6,N/A
V1 = VAR: User Part Number: UPN; Tolerance: N/A; part number: VAR_SM-27V,E013951,N/A,N/A,VISHAY,EZJ-Z1V270EA,SCD-014209,R0603H35,N/A; tolerance: N/A
W1 W2 W8-W11 = NCWP: User Part Number: UPN; part number: NCWP_TH-WP22,E002517,TPC45D22
Y1 = XTALACABM8: User Part Number: UPN; part number: XTALACABM8_SM-25.000MEGHZ,E012212,YSML126W98H29
Y2 = XTAL: User Part Number: UPN; part number: XTAL_SM-24MEGHZ,E014174,YSML197W126H59

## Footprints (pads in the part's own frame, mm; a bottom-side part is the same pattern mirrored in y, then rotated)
C0201
  rect 0.305x0.406 smd: 1(-0.318,0) 2(0.318,0)
C0402
  rect 0.889x0.813 smd: 1(-0.635,0) 2(0.635,0)
C0603
  rect 1.092x1.194 smd: 1(-0.851,0) 2(0.851,0)
C0805
  rect 1.295x1.6 smd: 1(-0.953,0) 2(0.953,0)
C1206
  rect 1.6x2.007 smd: 1(-1.397,0) 2(1.397,0)
C1206H71
  rect 1.6x2.007 smd: 1(-1.397,0) 2(1.397,0)
C1210
  rect 1.575x2.692 smd: 1(-1.397,0) 2(1.397,0)
C1210-2
  rect 1.575x2.692 smd: 1(-1.397,0) 2(1.397,0)
C7343-43
  rect 3.353x2.438 smd: N(2.6,0) P(-2.6,0)
C7343H162
  rect 2.591x2.413 smd: N(3.2,0) P(-3.2,0)
C-NET8P-0805
  rect 0.254x0.66 smd: 1(-0.75,-0.7) 2(-0.25,-0.7) 3(0.25,-0.7) 4(0.75,-0.7) 5(0.75,0.7) 6(0.25,0.7) 7(-0.25,0.7) 8(-0.75,0.7)
CNAMPHENOL132255-11
  rect 6.35x0.432 smd: 1(0,0)
  rect 6.35x1.524 hole 0.508: 2(0,4.25) 4(0,-4.25)
  round 0.305 smd: 3(0,4.25) 5(0,-4.25)
CNBERG2X10H346LD36
  rect 1.651x1.651 hole 1.143: 1(0,0)
  round 1.651 hole 1.143: 2(0,2.54) 3(2.54,0) 4(2.54,2.54) 5(5.08,0) 6(5.08,2.54) 7(7.62,0) 8(7.62,2.54) 9(10.16,0) 10(10.16,2.54) 11(12.7,0) 12(12.7,2.54) 13(15.24,0) 14(15.24,2.54) 15(17.78,0) 16(17.78,2.54) 17(20.32,0) 18(20.32,2.54) 19(22.86,0) 20(22.86,2.54)
CNFOXAS0A626-U2SN-7F
  round 2.362 hole 1.6 unplated: (-33.4,0)
  round 2.362 hole 1.092 unplated: (33.4,0)
  rect 0.356x2.007 smd: 1(-31.65,-4.1) 2(-31.35,4.1) 3(-31.05,-4.1) 4(-30.75,4.1) 5(-30.45,-4.1) 6(-30.15,4.1) 7(-29.85,-4.1) 8(-29.55,4.1) 9(-29.25,-4.1) 10(-28.95,4.1) 11(-28.65,-4.1) 12(-28.35,4.1) 13(-28.05,-4.1) 14(-27.75,4.1) 15(-27.45,-4.1) 16(-27.15,4.1) 17(-26.85,-4.1) 18(-26.55,4.1) 19(-26.25,-4.1) 20(-25.95,4.1) 21(-25.65,-4.1) 22(-25.35,4.1) 23(-25.05,-4.1) 24(-24.75,4.1) 25(-24.45,-4.1) 26(-24.15,4.1) 27(-23.85,-4.1) 28(-23.55,4.1) 29(-23.25,-4.1) 30(-22.95,4.1) 31(-22.65,-4.1) 32(-22.35,4.1) 33(-22.05,-4.1) 34(-21.75,4.1) 35(-21.45,-4.1) 36(-21.15,4.1) 37(-20.85,-4.1) 38(-20.55,4.1) 39(-20.25,-4.1) 40(-19.95,4.1) 41(-19.65,-4.1) 42(-19.35,4.1) 43(-19.05,-4.1) 44(-18.75,4.1) 45(-18.45,-4.1) 46(-18.15,4.1) 47(-17.85,-4.1) 48(-17.55,4.1) 49(-17.25,-4.1) 50(-16.95,4.1) 51(-16.65,-4.1) 52(-16.35,4.1) 53(-16.05,-4.1) 54(-15.75,4.1) 55(-15.45,-4.1) 56(-15.15,4.1) 57(-14.85,-4.1) 58(-14.55,4.1) 59(-14.25,-4.1) 60(-13.95,4.1) 61(-13.65,-4.1) 62(-13.35,4.1) 63(-13.05,-4.1) 64(-12.75,4.1) 65(-12.45,-4.1) 66(-12.15,4.1) 67(-11.85,-4.1) 68(-11.55,4.1) 69(-11.25,-4.1) 70(-10.95,4.1) 71(-10.65,-4.1) 72(-10.35,4.1) 73(-7.65,-4.1) 74(-7.35,4.1) 75(-7.05,-4.1) 76(-6.75,4.1) 77(-6.45,-4.1) 78(-6.15,4.1) 79(-5.85,-4.1) 80(-5.55,4.1) 81(-5.25,-4.1) 82(-4.95,4.1) 83(-4.65,-4.1) 84(-4.35,4.1) 85(-4.05,-4.1) 86(-3.75,4.1) 87(-3.45,-4.1) 88(-3.15,4.1) 89(-2.85,-4.1) 90(-2.55,4.1) 91(-2.25,-4.1) 92(-1.95,4.1) 93(-1.65,-4.1) 94(-1.35,4.1) 95(-1.05,-4.1) 96(-0.75,4.1) 97(-0.45,-4.1) 98(-0.15,4.1) 99(0.15,-4.1) 100(0.45,4.1) 101(0.75,-4.1) 102(1.05,4.1) 103(1.35,-4.1) 104(1.65,4.1) 105(1.95,-4.1) 106(2.25,4.1) 107(2.55,-4.1) 108(2.85,4.1) 109(3.15,-4.1) 110(3.45,4.1) 111(3.75,-4.1) 112(4.05,4.1) 113(4.35,-4.1) 114(4.65,4.1) 115(4.95,-4.1) 116(5.25,4.1) 117(5.55,-4.1) 118(5.85,4.1) 119(6.15,-4.1) 120(6.45,4.1) 121(6.75,-4.1) 122(7.05,4.1) 123(7.35,-4.1) 124(7.65,4.1) 125(7.95,-4.1) 126(8.25,4.1) 127(8.55,-4.1) 128(8.85,4.1) 129(9.15,-4.1) 130(9.45,4.1) 131(9.75,-4.1) 132(10.05,4.1) 133(10.35,-4.1) 134(10.65,4.1) 135(10.95,-4.1) 136(11.25,4.1) 137(11.55,-4.1) 138(11.85,4.1) 139(12.15,-4.1) 140(12.45,4.1) 141(12.75,-4.1) 142(13.05,4.1) 143(13.35,-4.1) 144(13.65,4.1) 145(13.95,-4.1) 146(14.25,4.1) 147(14.55,-4.1) 148(14.85,4.1) 149(15.15,-4.1) 150(15.45,4.1) 151(15.75,-4.1) 152(16.05,4.1) 153(16.35,-4.1) 154(16.65,4.1) 155(16.95,-4.1) 156(17.25,4.1) 157(17.55,-4.1) 158(17.85,4.1) 159(18.15,-4.1) 160(18.45,4.1) 161(18.75,-4.1) 162(19.05,4.1) 163(19.35,-4.1) 164(19.65,4.1) 165(19.95,-4.1) 166(20.25,4.1) 167(20.55,-4.1) 168(20.85,4.1) 169(21.15,-4.1) 170(21.45,4.1) 171(21.75,-4.1) 172(22.05,4.1) 173(22.35,-4.1) 174(22.65,4.1) 175(22.95,-4.1) 176(23.25,4.1) 177(23.55,-4.1) 178(23.85,4.1) 179(24.15,-4.1) 180(24.45,4.1) 181(24.75,-4.1) 182(25.05,4.1) 183(25.35,-4.1) 184(25.65,4.1) 185(25.95,-4.1) 186(26.25,4.1) 187(26.55,-4.1) 188(26.85,4.1) 189(27.15,-4.1) 190(27.45,4.1) 191(27.75,-4.1) 192(28.05,4.1) 193(28.35,-4.1) 194(28.65,4.1) 195(28.95,-4.1) 196(29.25,4.1) 197(29.55,-4.1) 198(29.85,4.1) 199(30.15,-4.1) 200(30.45,4.1) 201(30.75,-4.1) 202(31.05,4.1) 203(31.35,-4.1) 204(31.65,4.1)
  rect 3.505x4.597 smd: GND1(-32.8,12) GND2(32.8,12)
CNHDR2X7H380
  rect 1.27x3.683 smd: 1(-7.62,-2.477) 2(-7.62,2.477) 3(-5.08,-2.477) 4(-5.08,2.477) 5(-2.54,-2.477) 6(-2.54,2.477) 7(0,-2.477) 8(0,2.477) 9(2.54,-2.477) 10(2.54,2.477) 11(5.08,-2.477) 12(5.08,2.477) 13(7.62,-2.477) 14(7.62,2.477)
CNHDRRA2X3H451
  round 4.318 hole 2.997 unplated: (-0.013,7.29) (8.395,7.29)
  rect 2.286x2.286 hole 1.778: 1(0,0)
  round 2.286 hole 1.778: 2(4.191,0) 3(8.382,0) 4(0,-5.512) 5(4.191,-5.512) 6(8.382,-5.512)
CNLOOPTP
  round 2.159 hole 1.6: 1(0,0)
CNMOLEX22-23-2031
  rect 1.524x1.524 hole 1.016: 1(0,0)
  round 1.524 hole 1.016: 2(2.54,0) 3(5.08,0)
CNMOLEX87832-1420
  round 1.27 hole 1.016 unplated: (-5,0) (5,0)
  rect 0.991x2.743 smd: 1(-6,-2.122) 2(-6,2.122) 3(-4,-2.122) 4(-4,2.122) 5(-2,-2.122) 6(-2,2.122) 7(0,-2.122) 8(0,2.122) 9(2,-2.122) 10(2,2.122) 11(4,-2.122) 12(4,2.122) 13(6,-2.122) 14(6,2.122)
CNSAMTECASP-134486-01
  round 2.54 hole 1.27 unplated: (-27.178,3.048) (27.178,0)
  round 0.635 smd: A1(-24.765,5.715) A2(-23.495,5.715) A3(-22.225,5.715) A4(-20.955,5.715) A5(-19.685,5.715) A6(-18.415,5.715) A7(-17.145,5.715) A8(-15.875,5.715) A9(-14.605,5.715) A10(-13.335,5.715) A11(-12.065,5.715) A12(-10.795,5.715) A13(-9.525,5.715) A14(-8.255,5.715) A15(-6.985,5.715) A16(-5.715,5.715) A17(-4.445,5.715) A18(-3.175,5.715) A19(-1.905,5.715) A20(-0.635,5.715) A21(0.635,5.715) A22(1.905,5.715) A23(3.175,5.715) A24(4.445,5.715) A25(5.715,5.715) A26(6.985,5.715) A27(8.255,5.715) A28(9.525,5.715) A29(10.795,5.715) A30(12.065,5.715) A31(13.335,5.715) A32(14.605,5.715) A33(15.875,5.715) A34(17.145,5.715) A35(18.415,5.715) A36(19.685,5.715) A37(20.955,5.715) A38(22.225,5.715) A39(23.495,5.715) A40(24.765,5.715) B1(-24.765,4.445) B2(-23.495,4.445) B3(-22.225,4.445) B4(-20.955,4.445) B5(-19.685,4.445) B6(-18.415,4.445) B7(-17.145,4.445) B8(-15.875,4.445) B9(-14.605,4.445) B10(-13.335,4.445) B11(-12.065,4.445) B12(-10.795,4.445) B13(-9.525,4.445) B14(-8.255,4.445) B15(-6.985,4.445) B16(-5.715,4.445) B17(-4.445,4.445) B18(-3.175,4.445) B19(-1.905,4.445) B20(-0.635,4.445) B21(0.635,4.445) B22(1.905,4.445) B23(3.175,4.445) B24(4.445,4.445) B25(5.715,4.445) B26(6.985,4.445) B27(8.255,4.445) B28(9.525,4.445) B29(10.795,4.445) B30(12.065,4.445) B31(13.335,4.445) B32(14.605,4.445) B33(15.875,4.445) B34(17.145,4.445) B35(18.415,4.445) B36(19.685,4.445) B37(20.955,4.445) B38(22.225,4.445) B39(23.495,4.445) B40(24.765,4.445) C1(-24.765,3.175) C2(-23.495,3.175) C3(-22.225,3.175) C4(-20.955,3.175) C5(-19.685,3.175) C6(-18.415,3.175) C7(-17.145,3.175) C8(-15.875,3.175) C9(-14.605,3.175) C10(-13.335,3.175) C11(-12.065,3.175) C12(-10.795,3.175) C13(-9.525,3.175) C14(-8.255,3.175) C15(-6.985,3.175) C16(-5.715,3.175) C17(-4.445,3.175) C18(-3.175,3.175) C19(-1.905,3.175) C20(-0.635,3.175) C21(0.635,3.175) C22(1.905,3.175) C23(3.175,3.175) C24(4.445,3.175) C25(5.715,3.175) C26(6.985,3.175) C27(8.255,3.175) C28(9.525,3.175) C29(10.795,3.175) C30(12.065,3.175) C31(13.335,3.175) C32(14.605,3.175) C33(15.875,3.175) C34(17.145,3.175) C35(18.415,3.175) C36(19.685,3.175) C37(20.955,3.175) C38(22.225,3.175) C39(23.495,3.175) C40(24.765,3.175) D1(-24.765,1.905) D2(-23.495,1.905) D3(-22.225,1.905) D4(-20.955,1.905) D5(-19.685,1.905) D6(-18.415,1.905) D7(-17.145,1.905) D8(-15.875,1.905) D9(-14.605,1.905) D10(-13.335,1.905) D11(-12.065,1.905) D12(-10.795,1.905) D13(-9.525,1.905) D14(-8.255,1.905) D15(-6.985,1.905) D16(-5.715,1.905) D17(-4.445,1.905) D18(-3.175,1.905) D19(-1.905,1.905) D20(-0.635,1.905) D21(0.635,1.905) D22(1.905,1.905) D23(3.175,1.905) D24(4.445,1.905) D25(5.715,1.905) D26(6.985,1.905) D27(8.255,1.905) D28(9.525,1.905) D29(10.795,1.905) D30(12.065,1.905) D31(13.335,1.905) D32(14.605,1.905) D33(15.875,1.905) D34(17.145,1.905) D35(18.415,1.905) D36(19.685,1.905) D37(20.955,1.905) D38(22.225,1.905) D39(23.495,1.905) D40(24.765,1.905) E1(-24.765,0.635) E2(-23.495,0.635) E3(-22.225,0.635) E4(-20.955,0.635) E5(-19.685,0.635) E6(-18.415,0.635) E7(-17.145,0.635) E8(-15.875,0.635) E9(-14.605,0.635) E10(-13.335,0.635) E11(-12.065,0.635) E12(-10.795,0.635) E13(-9.525,0.635) E14(-8.255,0.635) E15(-6.985,0.635) E16(-5.715,0.635) E17(-4.445,0.635) E18(-3.175,0.635) E19(-1.905,0.635) E20(-0.635,0.635) E21(0.635,0.635) E22(1.905,0.635) E23(3.175,0.635) E24(4.445,0.635) E25(5.715,0.635) E26(6.985,0.635) E27(8.255,0.635) E28(9.525,0.635) E29(10.795,0.635) E30(12.065,0.635) E31(13.335,0.635) E32(14.605,0.635) E33(15.875,0.635) E34(17.145,0.635) E35(18.415,0.635) E36(19.685,0.635) E37(20.955,0.635) E38(22.225,0.635) E39(23.495,0.635) E40(24.765,0.635) F1(-24.765,-0.635) F2(-23.495,-0.635) F3(-22.225,-0.635) F4(-20.955,-0.635) F5(-19.685,-0.635) F6(-18.415,-0.635) F7(-17.145,-0.635) F8(-15.875,-0.635) F9(-14.605,-0.635) F10(-13.335,-0.635) F11(-12.065,-0.635) F12(-10.795,-0.635) F13(-9.525,-0.635) F14(-8.255,-0.635) F15(-6.985,-0.635) F16(-5.715,-0.635) F17(-4.445,-0.635) F18(-3.175,-0.635) F19(-1.905,-0.635) F20(-0.635,-0.635) F21(0.635,-0.635) F22(1.905,-0.635) F23(3.175,-0.635) F24(4.445,-0.635) F25(5.715,-0.635) F26(6.985,-0.635) F27(8.255,-0.635) F28(9.525,-0.635) F29(10.795,-0.635) F30(12.065,-0.635) F31(13.335,-0.635) F32(14.605,-0.635) F33(15.875,-0.635) F34(17.145,-0.635) F35(18.415,-0.635) F36(19.685,-0.635) F37(20.955,-0.635) F38(22.225,-0.635) F39(23.495,-0.635) F40(24.765,-0.635) G1(-24.765,-1.905) G2(-23.495,-1.905) G3(-22.225,-1.905) G4(-20.955,-1.905) G5(-19.685,-1.905) G6(-18.415,-1.905) G7(-17.145,-1.905) G8(-15.875,-1.905) G9(-14.605,-1.905) G10(-13.335,-1.905) G11(-12.065,-1.905) G12(-10.795,-1.905) G13(-9.525,-1.905) G14(-8.255,-1.905) G15(-6.985,-1.905) G16(-5.715,-1.905) G17(-4.445,-1.905) G18(-3.175,-1.905) G19(-1.905,-1.905) G20(-0.635,-1.905) G21(0.635,-1.905) G22(1.905,-1.905) G23(3.175,-1.905) G24(4.445,-1.905) G25(5.715,-1.905) G26(6.985,-1.905) G27(8.255,-1.905) G28(9.525,-1.905) G29(10.795,-1.905) G30(12.065,-1.905) G31(13.335,-1.905) G32(14.605,-1.905) G33(15.875,-1.905) G34(17.145,-1.905) G35(18.415,-1.905) G36(19.685,-1.905) G37(20.955,-1.905) G38(22.225,-1.905) G39(23.495,-1.905) G40(24.765,-1.905) H1(-24.765,-3.175) H2(-23.495,-3.175) H3(-22.225,-3.175) H4(-20.955,-3.175) H5(-19.685,-3.175) H6(-18.415,-3.175) H7(-17.145,-3.175) H8(-15.875,-3.175) H9(-14.605,-3.175) H10(-13.335,-3.175) H11(-12.065,-3.175) H12(-10.795,-3.175) H13(-9.525,-3.175) H14(-8.255,-3.175) H15(-6.985,-3.175) H16(-5.715,-3.175) H17(-4.445,-3.175) H18(-3.175,-3.175) H19(-1.905,-3.175) H20(-0.635,-3.175) H21(0.635,-3.175) H22(1.905,-3.175) H23(3.175,-3.175) H24(4.445,-3.175) H25(5.715,-3.175) H26(6.985,-3.175) H27(8.255,-3.175) H28(9.525,-3.175) H29(10.795,-3.175) H30(12.065,-3.175) H31(13.335,-3.175) H32(14.605,-3.175) H33(15.875,-3.175) H34(17.145,-3.175) H35(18.415,-3.175) H36(19.685,-3.175) H37(20.955,-3.175) H38(22.225,-3.175) H39(23.495,-3.175) H40(24.765,-3.175) J1(-24.765,-4.445) J2(-23.495,-4.445) J3(-22.225,-4.445) J4(-20.955,-4.445) J5(-19.685,-4.445) J6(-18.415,-4.445) J7(-17.145,-4.445) J8(-15.875,-4.445) J9(-14.605,-4.445) J10(-13.335,-4.445) J11(-12.065,-4.445) J12(-10.795,-4.445) J13(-9.525,-4.445) J14(-8.255,-4.445) J15(-6.985,-4.445) J16(-5.715,-4.445) J17(-4.445,-4.445) J18(-3.175,-4.445) J19(-1.905,-4.445) J20(-0.635,-4.445) J21(0.635,-4.445) J22(1.905,-4.445) J23(3.175,-4.445) J24(4.445,-4.445) J25(5.715,-4.445) J26(6.985,-4.445) J27(8.255,-4.445) J28(9.525,-4.445) J29(10.795,-4.445) J30(12.065,-4.445) J31(13.335,-4.445) J32(14.605,-4.445) J33(15.875,-4.445) J34(17.145,-4.445) J35(18.415,-4.445) J36(19.685,-4.445) J37(20.955,-4.445) J38(22.225,-4.445) J39(23.495,-4.445) J40(24.765,-4.445) K1(-24.765,-5.715) K2(-23.495,-5.715) K3(-22.225,-5.715) K4(-20.955,-5.715) K5(-19.685,-5.715) K6(-18.415,-5.715) K7(-17.145,-5.715) K8(-15.875,-5.715) K9(-14.605,-5.715) K10(-13.335,-5.715) K11(-12.065,-5.715) K12(-10.795,-5.715) K13(-9.525,-5.715) K14(-8.255,-5.715) K15(-6.985,-5.715) K16(-5.715,-5.715) K17(-4.445,-5.715) K18(-3.175,-5.715) K19(-1.905,-5.715) K20(-0.635,-5.715) K21(0.635,-5.715) K22(1.905,-5.715) K23(3.175,-5.715) K24(4.445,-5.715) K25(5.715,-5.715) K26(6.985,-5.715) K27(8.255,-5.715) K28(9.525,-5.715) K29(10.795,-5.715) K30(12.065,-5.715) K31(13.335,-5.715) K32(14.605,-5.715) K33(15.875,-5.715) K34(17.145,-5.715) K35(18.415,-5.715) K36(19.685,-5.715) K37(20.955,-5.715) K38(22.225,-5.715) K39(23.495,-5.715) K40(24.765,-5.715)
